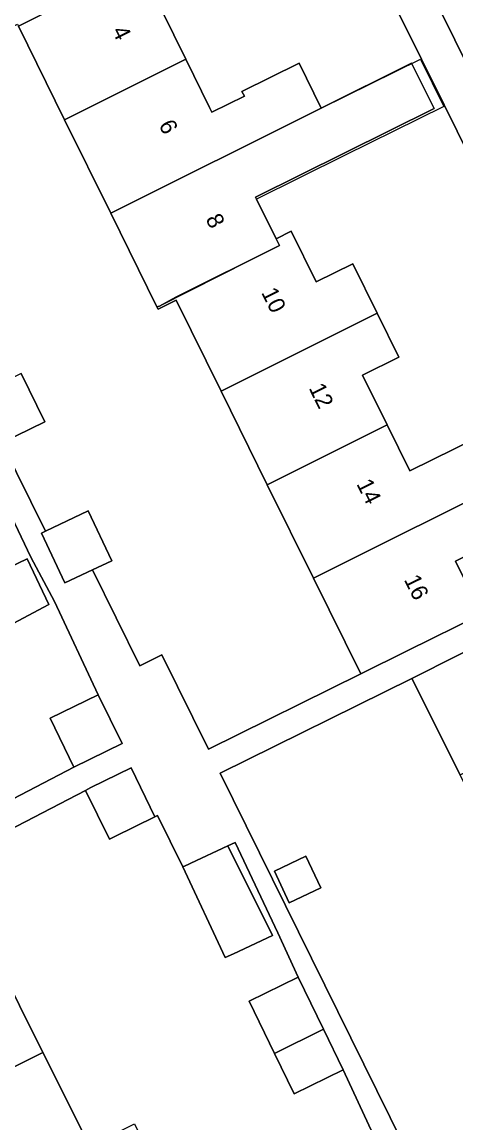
# Model space of a CAD drawing. Extents: x 157793 to 159380, y 380877 to 382313.
# Drawn here: x 158219.8 to 158246, y 381481.1 to 381547.4 of the extents above; entities that cross this region are included whole.
import ezdxf

# ---------------------------------------------------------------- set-up
doc = ezdxf.new("R2010")
doc.units = 0
for name, color, linetype in [('IMGEO_Erf', 7, 'Continuous'), ('IMGEO_Pand', 7, 'Continuous'), ('IMGEO_Pand_nummerreeks', 7, 'Continuous'), ('IMGEO_Pand_vergunning_verleend', 7, 'Continuous'), ('IMGEO_Rijbaan_lokaal_open', 7, 'Continuous'), ('IMGEO_Voetpad_open', 7, 'Continuous')]:
    doc.layers.add(name, color=color, linetype=linetype)

msp = doc.modelspace()

# ---------------------------------------------------------------- linework, layer by layer
at = {"layer": 'IMGEO_Erf'}
for points in [[(158228.253, 381548.103), (158229.702, 381545.17), (158231.135, 381542.27), (158231.277, 381541.984), (158233.232, 381542.95), (158233.09, 381543.236), (158236.528, 381544.935), (158237.867, 381542.226), (158243.307, 381544.94), (158244.663, 381542.201), (158233.896, 381536.872), (158233.96, 381536.744), (158235.14, 381534.36), (158236.06, 381534.814), (158237.566, 381531.766), (158239.769, 381532.855), (158241.242, 381529.873), (158242.547, 381527.232), (158240.35, 381526.146), (158241.831, 381523.149), (158243.2, 381520.38), (158248.582, 381523.039)], [(158245.268, 381542.416), (158242.545, 381547.917)], [(158219.772, 381526.237), (158221.2, 381523.343), (158218.612, 381522.066), (158221.24, 381516.749), (158223.822, 381517.971), (158225.244, 381514.966), (158224.084, 381514.417), (158226.936, 381508.647), (158228.252, 381509.297), (158231.063, 381503.61), (158240.248, 381508.149), (158237.397, 381513.918), (158234.615, 381519.548), (158231.833, 381525.177), (158229.126, 381530.655), (158228.04, 381530.118), (158227.967, 381530.266), (158225.184, 381535.898), (158222.402, 381541.527), (158219.62, 381547.158)], [(158255.147, 381522.693), (158252.294, 381528.223), (158245.268, 381542.416)], [(158212.434, 381497.057), (158222.963, 381502.539), (158221.523, 381505.478), (158224.429, 381506.901), (158221.79, 381512.505), (158220.367, 381515.18), (158219.018, 381518.02)], [(158251.283, 381517.575), (158245.955, 381514.942), (158247.533, 381511.749)], [(158257.493, 381479.518), (158254.705, 381485.101), (158252.153, 381483.826), (158249.33, 381489.481), (158251.883, 381490.755), (158249.059, 381496.41), (158247.267, 381500), (158246.237, 381502.064), (158243.334, 381507.879), (158231.775, 381502.167), (158247.523, 381470.3)], [(158241.894, 381478.465), (158239.196, 381484.306), (158236.243, 381482.861), (158235.055, 381485.29), (158233.515, 381488.436), (158236.468, 381489.881), (158235.241, 381492.55), (158232.679, 381498.005), (158232.228, 381497.793), (158234.926, 381492.402), (158232.578, 381491.299), (158232.084, 381491.067), (158229.522, 381496.522), (158227.994, 381499.623), (158227.845, 381499.55), (158225.417, 381498.361), (158225.103, 381498.207), (158223.667, 381501.139), (158215.352, 381496.827)], [(158218.262, 381491.01), (158221.092, 381485.355), (158223.921, 381479.701), (158226.602, 381481.047), (158227.662, 381478.929), (158225.983, 381477.435), (158225.241, 381477.063), (158226.601, 381474.344), (158226.869, 381474.478), (158227.604, 381474.845), (158230.582, 381468.893), (158233.411, 381463.239), (158235.914, 381464.491), (158238.783, 381458.757), (158237.493, 381458.111), (158239.187, 381454.726), (158230.245, 381450.253), (158225.61, 381459.335), (158224.056, 381462.381), (158214.071, 381457.386)]]:
    msp.add_lwpolyline(points, dxfattribs=at)
for points in [[(158217.92, 381514.017), (158220.147, 381515.075), (158221.449, 381512.324), (158219.003, 381511.023), (158218.806, 381510.918), (158217.446, 381513.792)], [(158235.042, 381496.278), (158236.947, 381497.173), (158237.844, 381495.265), (158235.938, 381494.37)]]:
    msp.add_lwpolyline(points, close=True, dxfattribs=at)
at = {"layer": 'IMGEO_Pand'}
for points in [[(158224.05, 381556.591), (158219.568, 381554.376), (158216.743, 381552.98), (158213.685, 381551.469), (158216.498, 381545.777), (158219.556, 381547.288), (158219.62, 381547.158), (158232.238, 381553.507), (158230.878, 381556.259), (158225.522, 381553.612)], [(158219.62, 381547.158), (158222.402, 381541.527), (158229.702, 381545.17), (158228.253, 381548.103), (158228.114, 381548.385), (158230.078, 381549.356), (158230.217, 381549.074), (158233.602, 381550.746), (158238.986, 381553.406), (158238.84, 381553.702), (158238.643, 381553.605), (158237.483, 381555.954), (158238.201, 381556.309), (158238.064, 381556.587), (158237.195, 381556.158), (158237.28, 381555.998), (158232.238, 381553.507)], [(158225.184, 381535.898), (158237.867, 381542.226), (158236.528, 381544.935), (158233.09, 381543.236), (158233.232, 381542.95), (158231.277, 381541.984), (158231.135, 381542.27), (158229.702, 381545.17), (158222.402, 381541.527)], [(158233.96, 381536.744), (158233.896, 381536.872), (158244.663, 381542.201), (158243.307, 381544.94), (158237.867, 381542.226), (158225.184, 381535.898), (158227.967, 381530.266), (158228.116, 381530.296), (158229.102, 381530.834), (158235.343, 381533.949), (158235.14, 381534.36)], [(158227.967, 381530.266), (158228.04, 381530.118), (158229.126, 381530.655), (158231.833, 381525.177), (158241.242, 381529.873), (158239.769, 381532.855), (158237.566, 381531.766), (158236.06, 381534.814), (158235.14, 381534.36), (158235.343, 381533.949), (158229.102, 381530.834), (158228.116, 381530.296)], [(158241.242, 381529.873), (158231.833, 381525.177), (158234.615, 381519.548), (158241.831, 381523.149), (158240.35, 381526.146), (158242.547, 381527.232)], [(158217.188, 381524.963), (158216.992, 381524.866), (158218.42, 381521.971), (158218.612, 381522.066), (158221.2, 381523.343), (158219.772, 381526.237)], [(158241.831, 381523.149), (158234.615, 381519.548), (158237.397, 381513.918), (158249.986, 381520.199), (158248.582, 381523.039), (158243.2, 381520.38)], [(158249.986, 381520.199), (158237.397, 381513.918), (158240.248, 381508.149), (158243.051, 381509.534), (158247.533, 381511.749), (158245.955, 381514.942), (158251.283, 381517.575)], [(158221.24, 381516.749), (158220.997, 381516.634), (158222.418, 381513.629), (158224.084, 381514.417), (158225.244, 381514.966), (158223.822, 381517.971)], [(158220.147, 381515.075), (158217.92, 381514.017), (158217.446, 381513.792), (158218.806, 381510.918), (158219.003, 381511.023), (158221.449, 381512.324)], [(158258.892, 381508.374), (158257.534, 381511.098), (158252.136, 381508.406), (158250.595, 381511.499), (158246.087, 381509.252), (158243.334, 381507.879), (158246.237, 381502.064)], [(158224.429, 381506.901), (158221.523, 381505.478), (158222.963, 381502.539), (158225.869, 381503.962)], [(158226.405, 381502.489), (158223.978, 381501.3), (158223.667, 381501.139), (158225.103, 381498.207), (158225.417, 381498.361), (158227.845, 381499.55)], [(158232.228, 381497.793), (158230.016, 381496.754), (158229.846, 381496.674), (158229.522, 381496.522), (158232.084, 381491.067), (158232.578, 381491.299), (158234.926, 381492.402)], [(158235.042, 381496.278), (158235.938, 381494.37), (158237.844, 381495.265), (158236.947, 381497.173)], [(158221.092, 381485.355), (158218.262, 381491.01), (158199.236, 381481.489), (158200.657, 381478.649), (158211.687, 381484.083), (158213.061, 381481.336)], [(158237.993, 381486.765), (158236.468, 381489.881), (158233.515, 381488.436), (158235.055, 381485.29)], [(158237.993, 381486.765), (158235.055, 381485.29), (158236.243, 381482.861), (158239.196, 381484.306)], [(158221.092, 381485.355), (158213.061, 381481.336), (158214.666, 381478.129), (158213.378, 381477.503), (158212.238, 381477.889), (158211.892, 381476.869), (158211.36, 381477.029), (158204.278, 381473.518), (158205.719, 381470.594), (158206.23, 381470.85), (158209.526, 381472.475), (158223.921, 381479.701)]]:
    msp.add_lwpolyline(points, close=True, dxfattribs=at)
at = {"layer": 'IMGEO_Pand_vergunning_verleend'}
msp.add_lwpolyline([(158225.184, 381535.898), (158237.867, 381542.226), (158243.846, 381545.181), (158245.257, 381542.328), (158239.277, 381539.372), (158233.96, 381536.744), (158235.14, 381534.36), (158235.343, 381533.949), (158228.116, 381530.296), (158227.967, 381530.266)], close=True, dxfattribs=at)
at = {"layer": 'IMGEO_Rijbaan_lokaal_open'}
msp.add_lwpolyline([(158227.014, 381594.882), (158225.89, 381597.35), (158225.527, 381598.112), (158221.342, 381595.998), (158252.296, 381533.479), (158256.481, 381535.423), (158252.887, 381542.755), (158249.583, 381549.497), (158245.054, 381558.421), (158235.941, 381576.836)], close=True, dxfattribs=at)
at = {"layer": 'IMGEO_Voetpad_open'}
for points in [[(158221.342, 381595.998), (158220.86, 381596.956), (158219.989, 381596.506), (158224.361, 381587.542), (158228.311, 381579.587), (158230.365, 381575.451), (158234.381, 381567.129), (158235.803, 381564.265), (158234.718, 381563.726), (158235.455, 381562.238), (158236.922, 381559.275), (158242.545, 381547.917), (158245.268, 381542.416), (158252.294, 381528.223), (158255.147, 381522.693)], [(158256.839, 381523.527), (158254.145, 381528.736), (158254.549, 381528.928), (158252.296, 381533.479), (158221.342, 381595.998)], [(158247.523, 381470.3), (158231.775, 381502.167), (158243.334, 381507.879), (158246.087, 381509.252), (158250.595, 381511.499), (158257.836, 381515.158), (158257.625, 381516.683), (158247.533, 381511.749), (158243.051, 381509.534), (158240.248, 381508.149), (158231.063, 381503.61), (158228.252, 381509.297), (158226.936, 381508.647), (158224.084, 381514.417), (158222.418, 381513.629), (158220.997, 381516.634), (158221.24, 381516.749), (158218.612, 381522.066)], [(158219.018, 381518.02), (158220.367, 381515.18), (158221.79, 381512.505), (158224.429, 381506.901), (158225.869, 381503.962), (158222.963, 381502.539), (158212.434, 381497.057)], [(158215.352, 381496.827), (158223.667, 381501.139), (158223.978, 381501.3), (158226.405, 381502.489), (158227.845, 381499.55), (158227.994, 381499.623), (158229.522, 381496.522), (158229.846, 381496.674), (158230.016, 381496.754), (158232.228, 381497.793), (158232.679, 381498.005), (158235.241, 381492.55), (158236.468, 381489.881), (158237.993, 381486.765), (158239.196, 381484.306), (158241.894, 381478.465)]]:
    msp.add_lwpolyline(points, dxfattribs=at)

# ---------------------------------------------------------------- texts
at = {"layer": 'IMGEO_Pand_nummerreeks'}
for s, rotation, p in [('4', 296.50834, (158225.227, 381546.883)), ('6', 296.50834, (158228.05, 381541.222)), ('8', 296.51055, (158230.875, 381535.558)), ('10', 296.44669, (158234.231, 381531.125)), ('12', 296.44669, (158237.097, 381525.364)), ('14', 296.44669, (158239.966, 381519.596)), ('16', 296.44669, (158242.834, 381513.83))]:
    msp.add_text(s, height=1, rotation=rotation, dxfattribs=at).set_placement(p)

doc.saveas('drawing.dxf')
